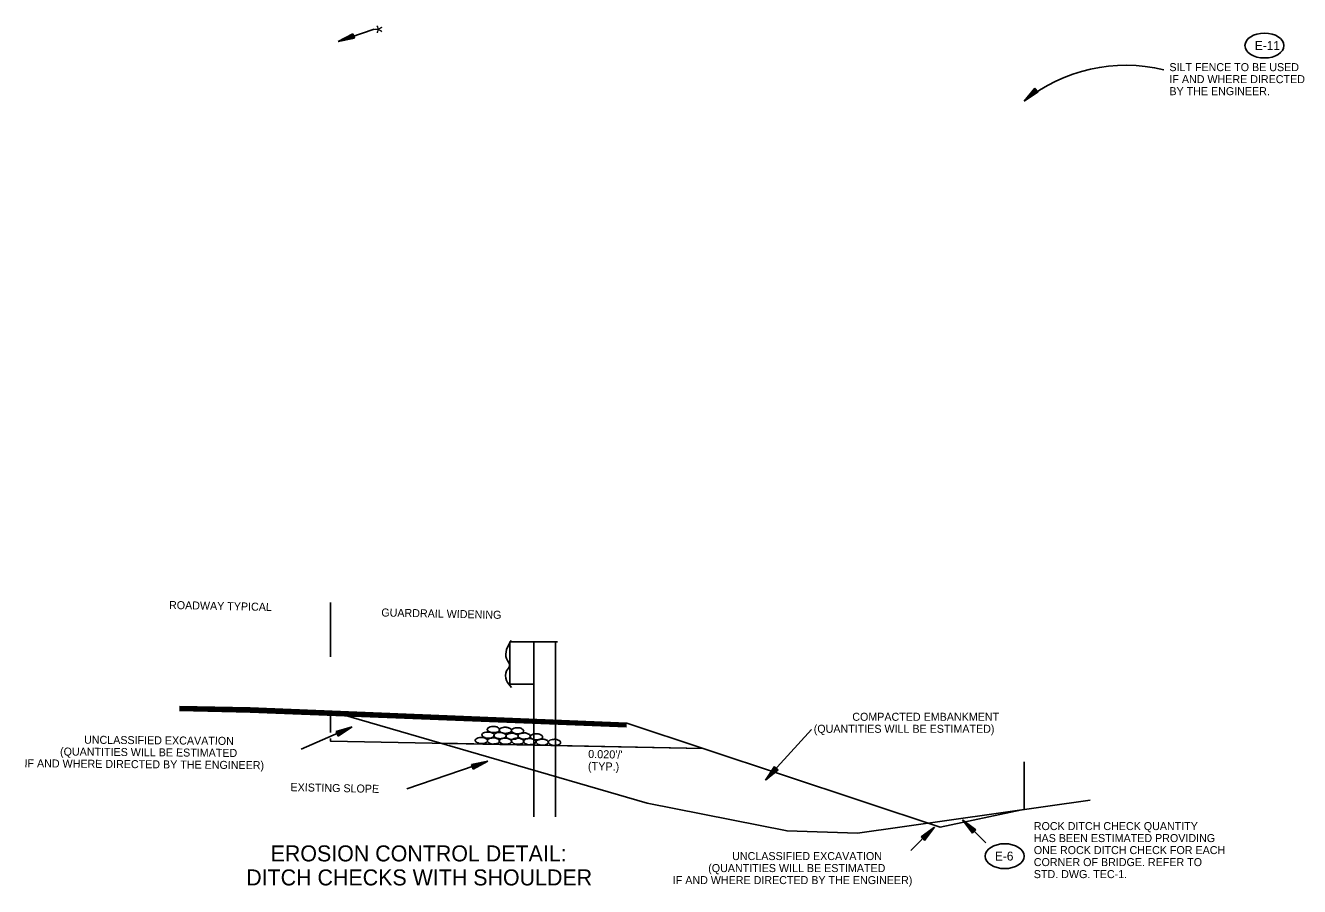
# Model space of a CAD drawing. Extents: x 1929624 to 1932072, y 596315 to 605954.
# Drawn here: x 1930601 to 1931557, y 605309 to 605954 of the extents above; entities that cross this region are included whole.
import ezdxf

# ---------------------------------------------------------------- set-up
doc = ezdxf.new("R2010")
doc.units = 0
doc.layers.add('B_Concrete hidden', color=7, linetype='Continuous')
doc.layers.add('Default', color=7, linetype='Continuous')

msp = doc.modelspace()

# ---------------------------------------------------------------- linework, layer by layer
at = {"layer": 'B_Concrete hidden'}
for p, q in [((1930830.08, 605481.03), (1930830.08, 605521.81)), ((1931109.71, 605412.27), (1930913.02, 605416.18)), ((1931350.33, 605366.61), (1931350.33, 605402.3))]:
    msp.add_line(p, q, dxfattribs=at)
for points in [[(1930830.08, 605440.25), (1931067.62, 605371.32), (1931172.51, 605350.45), (1931225.36, 605348.85), (1931399.81, 605373.56)], [(1930830.08, 605437.2), (1930830.08, 605424.36)], [(1930830.08, 605419.76), (1930830.08, 605417.83), (1931109.71, 605412.27)]]:
    msp.add_lwpolyline(points, dxfattribs=at)
for centre in [(1931530.51, 605939.11), (1931335.68, 605331.58)]:
    msp.add_ellipse(centre, major_axis=(14.6, 0), ratio=0.638788, dxfattribs=at)
at = {"layer": 'Default'}
for p, q in [((1930862.9, 605951.4), (1930835.81, 605942.2)), ((1930846.84, 605947.99), (1930835.81, 605942.2)), ((1930846.97, 605947.71), (1930837.74, 605942.86)), ((1930847.08, 605947.37), (1930839.81, 605943.6)), ((1930847.83, 605945.12), (1930839.81, 605943.6)), ((1930847.13, 605947.1), (1930841.73, 605944.26)), ((1930847.73, 605945.42), (1930841.73, 605944.26)), ((1930847.25, 605946.84), (1930843.66, 605944.95)), ((1930847.61, 605945.73), (1930843.66, 605944.95)), ((1930847.34, 605946.53), (1930845.62, 605945.64)), ((1930847.57, 605946.03), (1930845.62, 605945.64)), ((1930848.05, 605944.54), (1930846.84, 605947.99)), ((1930848.05, 605944.54), (1930835.81, 605942.2)), ((1930847.97, 605944.8), (1930837.74, 605942.86)), ((1931358.35, 605907.12), (1931350.37, 605897.54)), ((1931358.58, 605906.86), (1931351.93, 605898.89)), ((1931360.83, 605904.34), (1931358.35, 605907.12)), ((1931360.83, 605904.34), (1931350.37, 605897.54)), ((1931360.61, 605904.57), (1931351.93, 605898.89)), ((1931358.78, 605906.63), (1931353.49, 605900.32)), ((1931360.38, 605904.8), (1931353.49, 605900.32)), ((1931358.97, 605906.42), (1931355.02, 605901.69)), ((1931360.19, 605905.01), (1931355.02, 605901.69)), ((1931359.18, 605906.16), (1931356.57, 605903.06)), ((1931359.99, 605905.25), (1931356.57, 605903.06)), ((1931359.4, 605905.93), (1931358.15, 605904.44)), ((1931359.79, 605905.51), (1931358.15, 605904.44)), ((1930964.72, 605492.28), (1930964.72, 605460.45)), ((1930964.72, 605492.28), (1931000.37, 605492.28)), ((1930982.56, 605492.28), (1930982.56, 605361.1)), ((1930998.94, 605492.14), (1930998.94, 605360.97)), ((1930964.72, 605460.45), (1930982.56, 605460.45)), ((1930716.81, 605443.72), (1930769.98, 605442.66)), ((1930716.81, 605442.98), (1930769.98, 605441.92)), ((1930716.84, 605442.24), (1930769.98, 605441.18)), ((1930716.86, 605441.5), (1930769.98, 605440.44)), ((1930716.89, 605440.76), (1930769.93, 605439.71)), ((1930716.89, 605440.67), (1930769.98, 605439.61)), ((1930917.5, 605433.8), (1930769.88, 605439.71)), ((1930917.55, 605435.28), (1930769.93, 605441.18)), ((1930917.55, 605434.54), (1930769.93, 605440.44)), ((1930917.6, 605436.75), (1930769.98, 605442.66)), ((1930917.6, 605436.02), (1930769.98, 605441.92)), ((1930917.5, 605433.7), (1930769.98, 605439.61)), ((1930917.48, 605433.8), (1931052.14, 605428.41)), ((1930917.5, 605434.54), (1931052.16, 605429.15)), ((1930917.54, 605435.28), (1931052.19, 605429.89)), ((1930917.56, 605436.02), (1931052.22, 605430.63)), ((1930917.6, 605436.75), (1931052.26, 605431.37)), ((1931052.26, 605431.37), (1931287.27, 605353.24)), ((1930808.18, 605411.89), (1930840.18, 605425.68)), ((1930834.46, 605424.93), (1930846.42, 605428.41)), ((1930834.46, 605424.93), (1930835.98, 605421.61)), ((1930834.56, 605424.68), (1930844.56, 605427.58)), ((1930834.73, 605424.38), (1930842.57, 605426.64)), ((1930834.85, 605424.09), (1930840.72, 605425.8)), ((1930835, 605423.79), (1930838.87, 605424.94)), ((1930835.07, 605423.49), (1930836.98, 605424.07)), ((1930835.34, 605423.02), (1930836.98, 605424.07)), ((1930835.46, 605422.72), (1930838.87, 605424.94)), ((1930835.61, 605422.47), (1930840.72, 605425.8)), ((1930835.69, 605422.2), (1930842.57, 605426.64)), ((1930835.83, 605421.88), (1930844.56, 605427.58)), ((1930835.98, 605421.61), (1930846.42, 605428.41)), ((1931190.75, 605426.41), (1931157.25, 605389.86)), ((1930887.28, 605381.99), (1930948.19, 605402.67)), ((1930935.95, 605400.34), (1930948.19, 605402.67)), ((1930936.03, 605400.08), (1930946.26, 605402.01)), ((1930936.17, 605399.76), (1930944.19, 605401.28)), ((1930936.27, 605399.46), (1930942.27, 605400.61)), ((1930936.87, 605397.78), (1930942.27, 605400.61)), ((1930936.92, 605397.5), (1930944.19, 605401.28)), ((1930937.03, 605397.17), (1930946.26, 605402.01)), ((1930937.16, 605396.88), (1930948.19, 605402.67)), ((1930935.95, 605400.34), (1930937.16, 605396.88)), ((1930936.39, 605399.14), (1930940.34, 605399.93)), ((1930936.43, 605398.84), (1930938.38, 605399.24)), ((1930936.66, 605398.34), (1930938.38, 605399.24)), ((1930936.75, 605398.04), (1930940.34, 605399.93)), ((1931163.13, 605398.8), (1931156.22, 605388.43)), ((1931165.84, 605396.34), (1931156.22, 605388.43)), ((1931163.38, 605398.61), (1931157.6, 605389.93)), ((1931165.65, 605396.53), (1931157.6, 605389.93)), ((1931163.64, 605398.37), (1931159.06, 605391.58)), ((1931165.37, 605396.75), (1931159.06, 605391.58)), ((1931163.81, 605398.15), (1931160.43, 605393.08)), ((1931165.14, 605396.96), (1931160.43, 605393.08)), ((1931164.04, 605397.98), (1931161.79, 605394.6)), ((1931164.89, 605397.18), (1931161.79, 605394.6)), ((1931165.84, 605396.34), (1931163.13, 605398.8)), ((1931164.27, 605397.75), (1931163.19, 605396.14)), ((1931164.71, 605397.43), (1931163.19, 605396.14)), ((1931287.27, 605353.24), (1931348.62, 605366.31)), ((1931273.05, 605345.99), (1931283.12, 605353.34)), ((1931275.62, 605343.39), (1931283.12, 605353.34)), ((1931311.57, 605348.78), (1931304.07, 605358.73)), ((1931314.13, 605351.38), (1931304.07, 605358.73)), ((1931321.62, 605341.52), (1931305.45, 605357.63)), ((1931311.76, 605348.97), (1931305.51, 605357.29)), ((1931313.94, 605351.15), (1931305.51, 605357.29)), ((1931313.68, 605350.9), (1931307.09, 605355.75)), ((1931311.99, 605349.23), (1931307.09, 605355.75)), ((1931312.22, 605349.45), (1931308.53, 605354.33)), ((1931313.45, 605350.73), (1931308.53, 605354.33)), ((1931313.28, 605350.51), (1931310, 605352.9)), ((1931312.45, 605349.69), (1931310, 605352.9)), ((1931265.24, 605335.85), (1931281.41, 605351.96)), ((1931275.62, 605343.39), (1931273.05, 605345.99)), ((1931273.25, 605345.76), (1931281.67, 605351.9)), ((1931273.5, 605345.51), (1931280.1, 605350.36)), ((1931273.73, 605345.34), (1931278.65, 605348.94)), ((1931273.91, 605345.12), (1931277.19, 605347.51)), ((1931274.14, 605344.9), (1931275.71, 605346.05)), ((1931274.49, 605344.48), (1931275.71, 605346.05)), ((1931274.74, 605344.3), (1931277.19, 605347.51)), ((1931274.97, 605344.06), (1931278.65, 605348.94)), ((1931275.19, 605343.84), (1931280.1, 605350.36)), ((1931275.42, 605343.58), (1931281.67, 605351.9)), ((1931313.04, 605350.29), (1931311.48, 605351.44)), ((1931312.7, 605349.86), (1931311.48, 605351.44)), ((1931311.57, 605348.78), (1931314.13, 605351.38))]:
    msp.add_line(p, q, dxfattribs=at)
msp.add_arc((1931426.56, 605802.62), 121.72, 76.50197, 128.75222, dxfattribs=at)
for points in [[(1930965.58, 605493.32), (1930962.23, 605486.4), (1930962.06, 605479.66), (1930964.47, 605474.47), (1930962.23, 605470.53), (1930962.23, 605463.28), (1930965.78, 605458.04)], [(1930943.37, 605420.54), (1930941.75, 605420.49), (1930939.78, 605419.8), (1930938.84, 605418.92), (1930938.7, 605418.33), (1930939.19, 605417.34), (1930939.78, 605416.9), (1930940.81, 605416.41), (1930942.44, 605415.96), (1930943.22, 605415.91), (1930944.45, 605416.01), (1930945.78, 605416.26), (1930946.82, 605416.65), (1930947.75, 605417.44), (1930947.9, 605418.03), (1930947.6, 605418.92), (1930946.86, 605419.51), (1930946.18, 605420), (1930945.09, 605420.34), (1930944.4, 605420.49), (1930943.37, 605420.54)], [(1930948.39, 605424.63), (1930946.67, 605424.44), (1930944.75, 605423.94), (1930943.76, 605423.01), (1930943.62, 605422.47), (1930944.11, 605421.43), (1930944.7, 605420.99), (1930945.78, 605420.4), (1930947.36, 605420.01), (1930948.14, 605420.01), (1930949.37, 605420.11), (1930950.75, 605420.2), (1930951.79, 605420.7), (1930952.67, 605421.53), (1930952.82, 605422.17), (1930952.52, 605423.06), (1930951.79, 605423.65), (1930951.1, 605423.94), (1930950.01, 605424.39), (1930949.37, 605424.58), (1930948.39, 605424.63)], [(1930952.47, 605428.74), (1930950.84, 605428.64), (1930948.87, 605428.05), (1930947.84, 605427.12), (1930947.69, 605426.58), (1930948.19, 605425.59), (1930948.78, 605425.15), (1930949.91, 605424.61), (1930951.48, 605424.16), (1930952.32, 605424.16), (1930953.5, 605424.26), (1930954.83, 605424.41), (1930955.86, 605424.8), (1930956.75, 605425.64), (1930956.9, 605426.28), (1930956.6, 605427.17), (1930955.96, 605427.76), (1930955.27, 605428.15), (1930954.19, 605428.59), (1930953.5, 605428.74), (1930952.47, 605428.74)], [(1930952.47, 605420.25), (1930950.85, 605420.11), (1930948.88, 605419.51), (1930947.95, 605418.63), (1930947.8, 605418.04), (1930948.29, 605417.05), (1930948.78, 605416.61), (1930949.92, 605416.12), (1930951.44, 605415.63), (1930952.28, 605415.63), (1930953.51, 605415.73), (1930954.89, 605415.92), (1930955.87, 605416.27), (1930956.85, 605417.15), (1930957, 605417.74), (1930956.71, 605418.63), (1930955.97, 605419.22), (1930955.23, 605419.66), (1930954.2, 605420.06), (1930953.51, 605420.2), (1930952.47, 605420.25)], [(1930957.32, 605424.21), (1930955.7, 605424.16), (1930953.73, 605423.53), (1930952.75, 605422.59), (1930952.6, 605422.05), (1930953.14, 605421.02), (1930953.68, 605420.57), (1930954.76, 605420.08), (1930956.34, 605419.69), (1930957.17, 605419.59), (1930958.35, 605419.69), (1930959.68, 605419.93), (1930960.72, 605420.33), (1930961.7, 605421.11), (1930961.85, 605421.75), (1930961.55, 605422.64), (1930960.82, 605423.23), (1930960.13, 605423.67), (1930959.04, 605424.02), (1930958.35, 605424.16), (1930957.32, 605424.21)], [(1930961.32, 605420.12), (1930959.7, 605419.92), (1930957.73, 605419.38), (1930956.75, 605418.5), (1930956.6, 605417.91), (1930957.14, 605416.92), (1930957.68, 605416.48), (1930958.76, 605415.89), (1930960.29, 605415.5), (1930961.13, 605415.5), (1930962.36, 605415.59), (1930963.69, 605415.69), (1930964.72, 605416.14), (1930965.7, 605417.02), (1930965.85, 605417.61), (1930965.56, 605418.5), (1930964.82, 605419.09), (1930964.08, 605419.43), (1930963, 605419.83), (1930962.36, 605420.07), (1930961.32, 605420.12)], [(1930961.28, 605428.22), (1930959.66, 605428.12), (1930957.74, 605427.43), (1930956.76, 605426.64), (1930956.61, 605426.1), (1930957.15, 605425.07), (1930957.59, 605424.53), (1930958.77, 605424.03), (1930960.25, 605423.69), (1930961.09, 605423.59), (1930962.32, 605423.64), (1930963.69, 605423.89), (1930964.68, 605424.33), (1930965.71, 605425.12), (1930965.86, 605425.76), (1930965.56, 605426.64), (1930964.83, 605427.28), (1930964.09, 605427.63), (1930963.01, 605427.97), (1930962.32, 605428.12), (1930961.28, 605428.22)], [(1930966.42, 605423.71), (1930964.79, 605423.57), (1930962.82, 605423.02), (1930961.79, 605422.09), (1930961.64, 605421.55), (1930962.18, 605420.56), (1930962.73, 605420.12), (1930963.86, 605419.48), (1930965.38, 605419.14), (1930966.22, 605419.14), (1930967.4, 605419.24), (1930968.83, 605419.28), (1930969.81, 605419.78), (1930970.75, 605420.61), (1930970.89, 605421.25), (1930970.6, 605422.14), (1930969.91, 605422.73), (1930969.17, 605423.07), (1930968.14, 605423.42), (1930967.45, 605423.71), (1930966.42, 605423.71)], [(1930970.46, 605427.85), (1930968.84, 605427.8), (1930966.87, 605427.11), (1930965.88, 605426.22), (1930965.74, 605425.63), (1930966.28, 605424.65), (1930966.82, 605424.21), (1930967.9, 605423.71), (1930969.48, 605423.27), (1930970.31, 605423.22), (1930971.49, 605423.32), (1930972.82, 605423.57), (1930973.86, 605423.96), (1930974.84, 605424.75), (1930974.99, 605425.34), (1930974.69, 605426.22), (1930973.95, 605426.81), (1930973.26, 605427.31), (1930972.18, 605427.65), (1930971.49, 605427.8), (1930970.46, 605427.85)], [(1930970.58, 605420.13), (1930968.91, 605419.93), (1930966.94, 605419.39), (1930965.96, 605418.51), (1930965.81, 605417.92), (1930966.35, 605416.93), (1930966.89, 605416.49), (1930968.02, 605415.85), (1930969.55, 605415.5), (1930970.34, 605415.5), (1930971.57, 605415.55), (1930972.94, 605415.7), (1930973.98, 605416.14), (1930974.91, 605417.03), (1930975.06, 605417.62), (1930974.77, 605418.51), (1930974.03, 605419.1), (1930973.29, 605419.44), (1930972.26, 605419.79), (1930971.62, 605419.98), (1930970.58, 605420.13)], [(1930975.37, 605423.94), (1930973.75, 605423.75), (1930971.83, 605423.25), (1930970.85, 605422.32), (1930970.7, 605421.78), (1930971.24, 605420.74), (1930971.78, 605420.3), (1930972.86, 605419.71), (1930974.44, 605419.32), (1930975.22, 605419.32), (1930976.46, 605419.42), (1930977.78, 605419.51), (1930978.87, 605420.01), (1930979.8, 605420.84), (1930979.95, 605421.48), (1930979.65, 605422.37), (1930978.92, 605422.96), (1930978.18, 605423.25), (1930977.14, 605423.75), (1930976.41, 605423.89), (1930975.37, 605423.94)], [(1930979.65, 605419.76), (1930977.93, 605419.56), (1930976.06, 605419.07), (1930975.03, 605418.14), (1930974.88, 605417.6), (1930975.42, 605416.56), (1930975.96, 605416.12), (1930977.09, 605415.53), (1930978.62, 605415.14), (1930979.41, 605415.14), (1930980.64, 605415.23), (1930982.06, 605415.33), (1930983.05, 605415.82), (1930983.98, 605416.66), (1930984.13, 605417.3), (1930983.84, 605418.19), (1930983.1, 605418.78), (1930982.41, 605419.07), (1930981.33, 605419.47), (1930980.69, 605419.71), (1930979.65, 605419.76)], [(1930984.67, 605423.3), (1930983.05, 605423.25), (1930981.08, 605422.61), (1930980.1, 605421.68), (1930979.95, 605421.14), (1930980.49, 605420.11), (1930981.03, 605419.66), (1930982.11, 605419.17), (1930983.69, 605418.78), (1930984.53, 605418.68), (1930985.71, 605418.78), (1930987.03, 605419.02), (1930988.07, 605419.42), (1930989.05, 605420.2), (1930989.2, 605420.84), (1930988.9, 605421.73), (1930988.17, 605422.32), (1930987.48, 605422.76), (1930986.39, 605423.11), (1930985.71, 605423.25), (1930984.67, 605423.3)], [(1930988.93, 605419.38), (1930987.31, 605419.28), (1930985.39, 605418.6), (1930984.4, 605417.81), (1930984.25, 605417.27), (1930984.8, 605416.23), (1930985.24, 605415.69), (1930986.42, 605415.2), (1930987.9, 605414.86), (1930988.73, 605414.76), (1930989.96, 605414.81), (1930991.34, 605415.05), (1930992.32, 605415.5), (1930993.36, 605416.28), (1930993.51, 605416.92), (1930993.21, 605417.81), (1930992.47, 605418.45), (1930991.73, 605418.79), (1930990.65, 605419.14), (1930989.96, 605419.28), (1930988.93, 605419.38)], [(1930998.18, 605419.19), (1930996.56, 605419.05), (1930994.59, 605418.46), (1930993.65, 605417.57), (1930993.51, 605416.98), (1930994, 605416), (1930994.49, 605415.55), (1930995.62, 605415.06), (1930997.15, 605414.57), (1930997.98, 605414.57), (1930999.21, 605414.67), (1931000.59, 605414.86), (1931001.58, 605415.21), (1931002.56, 605416.09), (1931002.71, 605416.69), (1931002.41, 605417.57), (1931001.67, 605418.16), (1931000.94, 605418.6), (1930999.9, 605419), (1930999.21, 605419.15), (1930998.18, 605419.19)]]:
    msp.add_spline(points, degree=3, dxfattribs=at)

# ---------------------------------------------------------------- texts
at = {"layer": 'B_Concrete hidden'}
for s, p in [('E-11', (1931523.29, 605935.83)), ('E-6', (1931328.41, 605328.3))]:
    msp.add_text(s, height=6.663, rotation=360, dxfattribs=at).set_placement(p)
at = {"layer": 'Default'}
for s, height, rotation, p in [('*', 12, 90, (1930874.91, 605948.14)), ('ROADWAY TYPICAL', 6, 358.8537, (1930708.99, 605516.85)), ('GUARDRAIL WIDENING', 6, 358.8537, (1930868.18, 605511.23)), ('UNCLASSIFIED EXCAVATION', 6, 359.52696, (1930645.3, 605415.86)), ('(QUANTITIES WILL BE ESTIMATED', 6, 359.52696, (1930627.29, 605407.01)), ("0.020'/'", 6.075, 358.8537, (1931023.31, 605405.17)), ('IF AND WHERE DIRECTED BY THE ENGINEER)', 6, 359.52696, (1930600.65, 605398.23)), ('(TYP.)', 6.075, 358.8537, (1931023.13, 605396.06)), ('EXISTING SLOPE', 6, 358.8537, (1930800.1, 605380.32)), ('EROSION CONTROL DETAIL:', 12, 360, (1930785.21, 605327.65)), ('DITCH CHECKS WITH SHOULDER', 12, 360, (1930766.9, 605309.65))]:
    msp.add_text(s, height=height, rotation=rotation, dxfattribs=at).set_placement(p)
for s, p in [('SILT FENCE TO BE USED ', (1931459.23, 605919.92)), ('IF AND WHERE DIRECTED', (1931459.23, 605910.92)), ('BY THE ENGINEER. ', (1931459.23, 605901.92)), (' COMPACTED EMBANKMENT', (1931219.2, 605433.04)), ('(QUANTITIES WILL BE ESTIMATED)', (1931192.52, 605424.04)), ('ROCK DITCH CHECK QUANTITY ', (1931357.55, 605351.13)), ('HAS BEEN ESTIMATED PROVIDING', (1931357.55, 605342.13)), ('UNCLASSIFIED EXCAVATION', (1931131.33, 605328.65)), ('ONE ROCK DITCH CHECK FOR EACH', (1931357.55, 605333.13)), ('(QUANTITIES WILL BE ESTIMATED', (1931113.38, 605319.65)), ('CORNER OF BRIDGE. REFER TO', (1931357.55, 605324.13)), ('IF AND WHERE DIRECTED BY THE ENGINEER)', (1931086.82, 605310.65)), ('STD. DWG. TEC-1. ', (1931357.55, 605315.13))]:
    msp.add_text(s, height=6, dxfattribs=at).set_placement(p)

doc.saveas('drawing.dxf')
